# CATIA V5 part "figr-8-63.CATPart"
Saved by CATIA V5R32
Part number: Part1
Bounding box of the stored display mesh (mm): x -68.924 to 54.237, y -54.052 to 120.856, z 0 to 40
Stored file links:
  D:\PROJECTS\Project 2022\CATIA V5 6R 2022\Resources\Part Files\c08_catia_v5_6r2022_prt\figr-8-63.CATPart
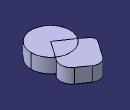
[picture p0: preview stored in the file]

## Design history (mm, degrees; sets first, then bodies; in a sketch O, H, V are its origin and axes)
Body1 (main body)
  Sketch1 on xy-plane, origin (0, 0, 0), H (1, 0, 0), V (0, 1, 0)
    circle A1 centre (0, 0) radius 54.2371
    point P1 (0, 54.2371)
    coincidence: A1 P1, P1 V
  Pad1: profile Sketch1, direction (0, 0, 1), length 40
Body2
  Sketch2 on xy-plane, origin (0, 0, 0), H (1, 0, 0), V (0, 1, 0)
    line L1 (0, 0) -> (36.9865, 52.8223)
    arc A1 centre (11.6298, 70.5772) radius 30.9549 from (36.9865, 52.8223) to (29.3848, 95.934) ccw
    line L2 (29.3848, 95.934) -> (0.2008, 116.3688)
    arc A2 centre (-14.1853, 95.8234) radius 25.0814 from (0.2008, 116.3688) to (-34.7307, 110.2094) ccw
    line L3 (-34.7307, 110.2094) -> (-66.0893, 65.4248)
    arc A3 centre (-53.2403, 56.4279) radius 15.6856 from (-66.0893, 65.4248) to (-62.2373, 43.579) ccw
    line L4 (-62.2373, 43.579) -> (0, 0)
    tangency: A1 L1, L2 A1, A2 L2, L3 A2, A3 L3, L4 A3
  Pad2: profile Sketch2, direction (0, 0, 1), length 40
